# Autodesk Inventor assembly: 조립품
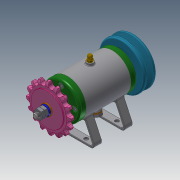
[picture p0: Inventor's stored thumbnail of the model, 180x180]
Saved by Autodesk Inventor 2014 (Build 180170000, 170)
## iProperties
Created: 2021-12
Part Number: 조립품
Document SubType Name: Assembly
Designer: dg
Author: dg
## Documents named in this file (16)
- C:\Users\dg\Desktop\711206v1010\조립품.iam
- C:\Users\dg\Desktop\711206v1010\본체.ipt
- C:\Users\dg\Desktop\711206v1010\V벨트풀리.ipt
- C:\Users\dg\Desktop\711206v1010\너트 M8.ipt
- C:\Users\dg\Desktop\711206v1010\니플 M6 x 0.75.ipt
- C:\Users\dg\Desktop\711206v1010\베어링 6002.ipt
- C:\Users\dg\Desktop\711206v1010\볼트 M4 x 12.ipt
- C:\Users\dg\Desktop\711206v1010\볼트 M6 x 8.ipt
- C:\Users\dg\Desktop\711206v1010\스프로킷.ipt
- C:\Users\dg\Desktop\711206v1010\스프링와셔 8.ipt
- C:\Users\dg\Desktop\711206v1010\오일 실 15 x 25 x 7.ipt
- C:\Users\dg\Desktop\711206v1010\와셔 6 x 11.5.ipt
- C:\Users\dg\Desktop\711206v1010\와셔 8 x 17.ipt
- C:\Users\dg\Desktop\711206v1010\축.ipt
- C:\Users\dg\Desktop\711206v1010\커버.ipt
- C:\Users\dg\Desktop\711206v1010\키 3 x 3.ipt
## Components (11 placed, 3 different names)
1. V벨트풀리:1
2. KS B 2023 6002 - 15 x 32 x 9:1
3. KS B 2023 6002 - 15 x 32 x 9:2
4. ISO 4762 M4 x 12:2
5. ISO 4762 M4 x 12:3
6. ISO 4762 M4 x 12:4
7. ISO 4762 M4 x 12:5
8. ISO 4762 M4 x 12:1
9. ISO 4762 M4 x 12:6
10. ISO 4762 M4 x 12:7
11. ISO 4762 M4 x 12:8
## Named parameters: d2_d1 = 0, d3_d0 = 0, d18_d15 = 0, d19_d16 = 0, d20_d17 = 0
